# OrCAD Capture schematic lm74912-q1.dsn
size D; title: LM74912-Q1 Automotive Ideal Diode With Circuit Breaker,; rev: 1.0; note: Datasheet: SNOSDE8A; note: Undervoltage and Overvoltage Protection With Fault Output
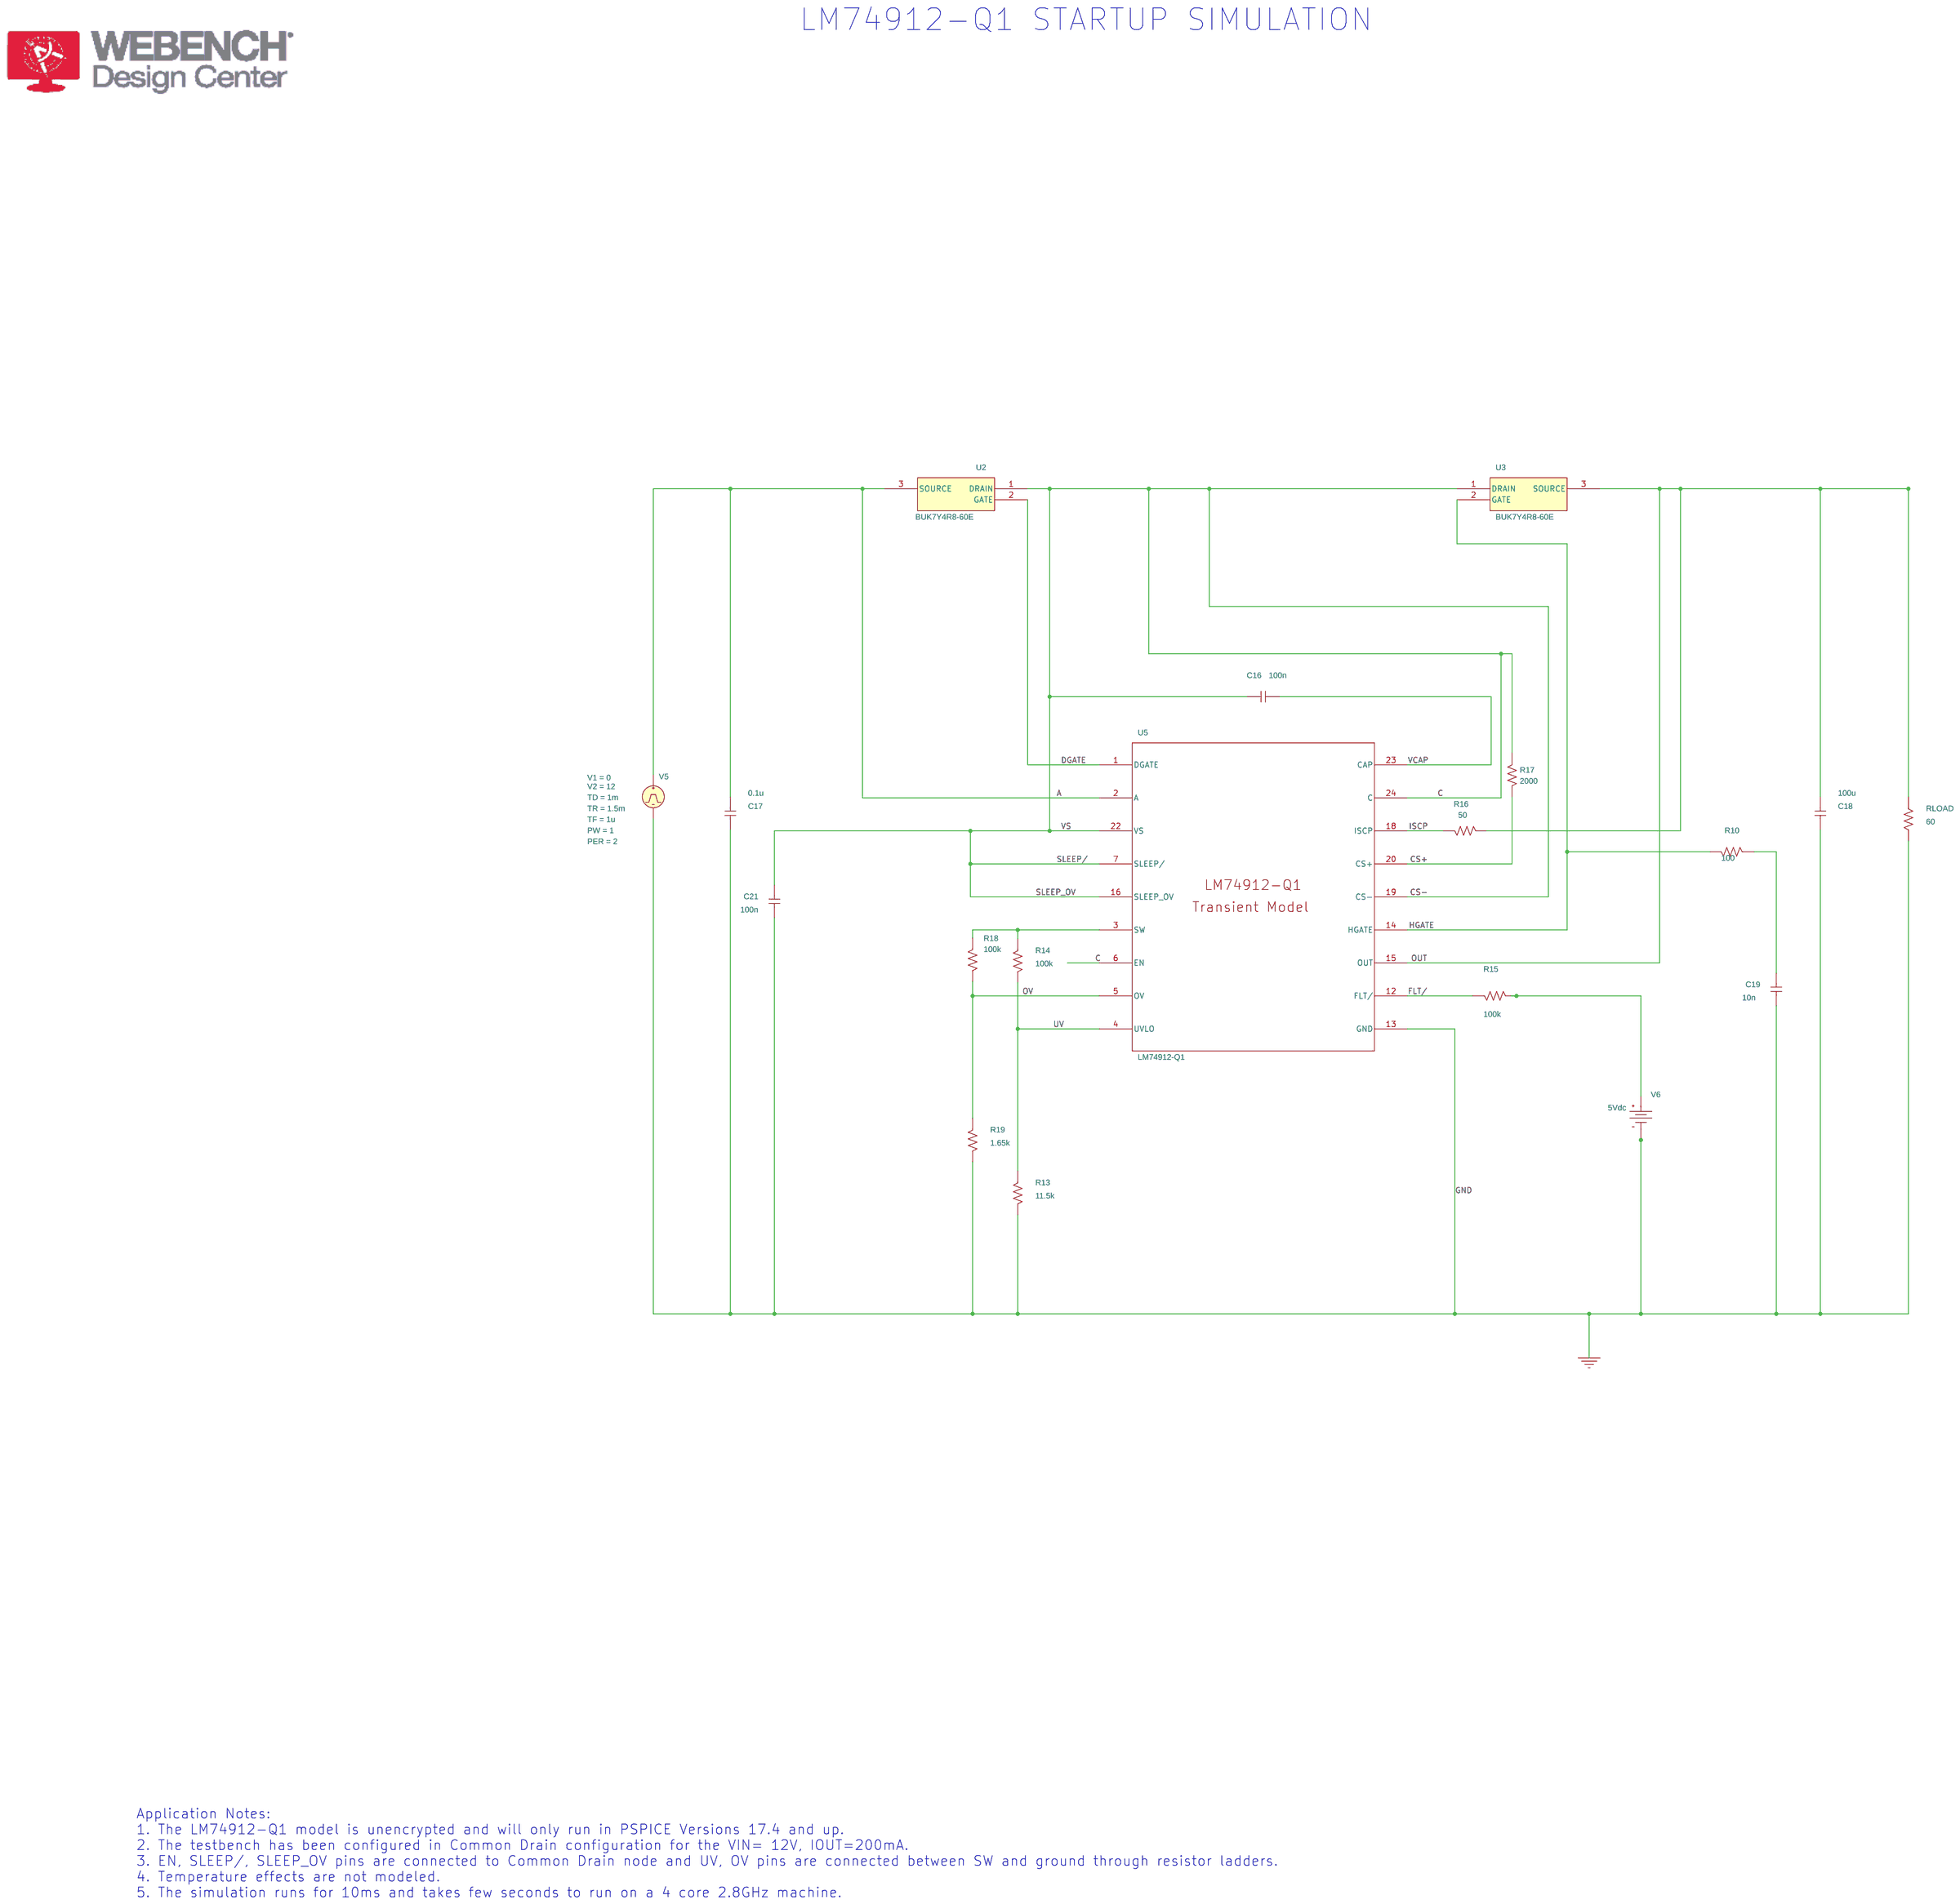
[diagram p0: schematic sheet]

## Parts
C16  100n  [RAD/CK05]
C17  0.1u  [RAD/CK05]
C18  100u  [RAD/CK05]
C19  10n  [RAD/CK05]
C21  100n  [RAD/CK05]
R10  100  [AX/RC05]
R13  11.5k  [AX/RC05]
R14  100k  [AX/RC05]
R15  100k  [AX/RC05]
R16  50  [AX/RC05]
R17  2000  [AX/RC05]
R18  100k  [AX/RC05]
R19  1.65k  [AX/RC05]
RLOAD  60  [AX/RC05]
U2  BUK7Y4R8-60E
U3  BUK7Y4R8-60E
U5  LM74912-Q1
V5  VPULSE
V6  VDC

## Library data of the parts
C16-C19 C21 = C
R10 R13-R19 RLOAD = R
U2 U3 = BUK7Y4R8-60E
U5 = LM74912_A
V5 = VPULSE: PER: 2; PW: 1; TD: 1m; TF: 1u; TR: 1.5m; V1: 0; V2: 12
V6 = VDC: DC: 5Vdc

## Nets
0: C17.2 C18.2 C19.1 C21.1 R13.2 R19.2 RLOAD.2 U5.13(GND) V5.2(-) V6.1(-)
A: C17.1 U2.3(SOURCE) U5.2(A) V5.1(+)
C: C16.1 C21.2 R17.1 U2.1(DRAIN) U3.1(DRAIN) U5.6(EN) U5.7(SLEEP/) U5.16(SLEEP_OV) U5.19(CS-) U5.22(VS) U5.24(C)
CS+: R17.2 U5.20(CS+)
DGATE: U2.2(GATE) U5.1(DGATE)
FLT/: R15.1 U5.12(FLT/)
HGATE: R10.2 U3.2(GATE) U5.14(HGATE)
ISCP: R16.1 U5.18(ISCP)
OUT: C18.1 R16.2 RLOAD.1 U3.3(SOURCE) U5.15(OUT)
OV: R18.2 R19.1 U5.5(OV)
UV: R13.1 R14.2 U5.4(UVLO)
VCAP: C16.2 U5.23(CAP)
N16773756: C19.2 R10.1
N16774012: R14.1 R18.1 U5.3(SW)
N16774044: R15.2 V6.0(+)

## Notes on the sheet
- LM74912-Q1 STARTUP SIMULATION
- Application Notes:
  1. The LM74912-Q1 model is unencrypted and will only run in PSPICE Versions 17.4 and up.
  2. The testbench has been configured in Common Drain configuration for the VIN= 12V, IOUT=200mA.
  3. EN, SLEEP/, SLEEP_OV pins are connected to Common Drain node and UV, OV pins are connected between SW and ground through resistor ladders.
  4. Temperature effects are not modeled.
  5. The simulation runs for 10ms and takes few seconds to run on a 4 core 2.8GHz machine.
